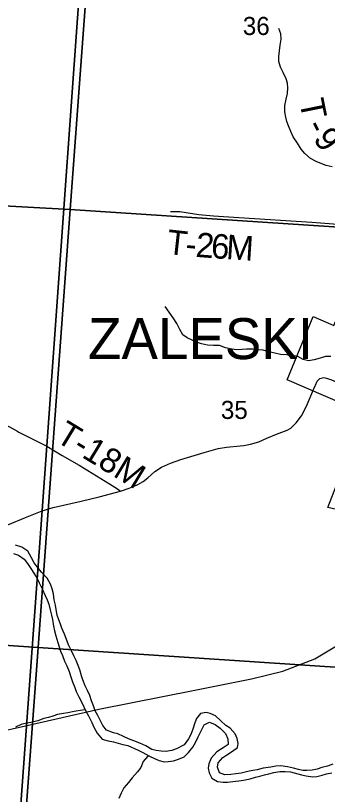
# Model space of a CAD drawing. Extents: x 0 to 34, y 0 to 22.
# Drawn here: x 5.215 to 5.937, y 16.597 to 18.398 of the extents above; entities that cross this region are included whole.
import ezdxf

# ---------------------------------------------------------------- set-up
doc = ezdxf.new("R2010")
doc.units = 0
for name, color, linetype in [('GM_X_Corporation', 7, 'Continuous'), ('GM_X_Corporation_Text', 7, 'Continuous'), ('GM_X_Major_River', 7, 'Continuous'), ('GM_X_Minor_River', 7, 'Continuous'), ('GM_X_Rail_Line', 7, 'Continuous'), ('GM_X_Section', 7, 'Continuous'), ('GM_X_Section_Text', 7, 'Continuous'), ('GM_X_State_Route', 7, 'Continuous'), ('GM_X_Township_Road', 7, 'Continuous'), ('GM_X_Township_Road_Text', 7, 'Continuous'), ('SC_Scratch1', 7, 'Continuous')]:
    doc.layers.add(name, color=color, linetype=linetype)

msp = doc.modelspace()

# ---------------------------------------------------------------- linework, layer by layer
at = {"layer": 'GM_X_Corporation'}
msp.add_lwpolyline([(6.2264, 17.1339), (6.0126, 17.2209), (6.0141, 17.2532), (5.9678, 17.2531), (5.9382, 17.2604), (6.023, 17.4781), (5.8434, 17.5552), (5.9039, 17.7022), (5.952, 17.6811), (6.1661, 18.1773), (6.6117, 17.9917), (6.5173, 17.6859), (6.5005, 17.6619), (6.4701, 17.6297), (6.4392, 17.6123), (6.4283, 17.605)], close=True, dxfattribs=at)
at = {"layer": 'GM_X_Major_River'}
for points in [[(5.7642, 16.6523), (5.7525, 16.6498), (5.7369, 16.6461), (5.7251, 16.6443), (5.713, 16.6428), (5.6997, 16.6422), (5.6872, 16.6464), (5.6827, 16.6598), (5.6843, 16.6696), (5.6946, 16.6821), (5.7042, 16.6884), (5.7171, 16.6967), (5.7285, 16.705), (5.7305, 16.7148), (5.7283, 16.7258), (5.7231, 16.7365), (5.7121, 16.7498), (5.702, 16.7564), (5.6903, 16.7671), (5.6774, 16.7782), (5.6657, 16.784), (5.6562, 16.7859), (5.643, 16.7837), (5.6334, 16.7724), (5.6299, 16.7626), (5.6253, 16.7478), (5.621, 16.735), (5.6149, 16.7251), (5.6049, 16.7116), (5.5878, 16.7018), (5.5764, 16.6981), (5.5627, 16.6959), (5.5521, 16.6964), (5.5407, 16.6984), (5.5305, 16.7003), (5.5162, 16.7088), (5.5025, 16.715), (5.4885, 16.7204), (5.4761, 16.7254), (5.4651, 16.7308), (5.4515, 16.7366), (5.4413, 16.7393), (5.4257, 16.7455), (5.4167, 16.7558), (5.4115, 16.7669), (5.4051, 16.779), (5.3991, 16.7897), (5.3954, 16.8015), (5.3905, 16.8129), (5.3868, 16.8255), (5.3816, 16.8369), (5.3756, 16.8476), (5.3707, 16.8613), (5.3678, 16.8708), (5.3637, 16.8845), (5.36, 16.8951), (5.3551, 16.9061), (5.3495, 16.9168), (5.3446, 16.9286), (5.3375, 16.9427), (5.3323, 16.9575), (5.3282, 16.9674), (5.3222, 16.9811), (5.3185, 16.9907), (5.3148, 17.0005), (5.3114, 17.0112), (5.3085, 17.0245), (5.307, 17.0344), (5.3045, 17.0469), (5.3023, 17.0602), (5.2997, 17.0724), (5.2956, 17.083), (5.2877, 17.0967), (5.2749, 17.1109), (5.2648, 17.1231), (5.258, 17.1326), (5.2509, 17.1456), (5.243, 17.1593), (5.229, 17.1681), (5.2146, 17.1732)], [(5.2103, 17.1538), (5.2217, 17.1503), (5.2349, 17.1404), (5.2428, 17.1305), (5.2503, 17.119), (5.2574, 17.108), (5.265, 17.0958), (5.2694, 17.0862), (5.2766, 17.0722), (5.2837, 17.0569), (5.2881, 17.0466), (5.2915, 17.0364), (5.2952, 17.0238), (5.2981, 17.0109), (5.3004, 17.001), (5.3029, 16.9855), (5.3051, 16.9748), (5.3081, 16.9634), (5.3125, 16.9478), (5.3155, 16.9379), (5.3192, 16.9277), (5.3237, 16.9181), (5.3282, 16.9052), (5.3334, 16.8942), (5.339, 16.8812), (5.3424, 16.8706), (5.3468, 16.8573), (5.3517, 16.8443), (5.355, 16.8344), (5.3614, 16.8222), (5.3666, 16.812), (5.3726, 16.7994), (5.3779, 16.7895), (5.3839, 16.7781), (5.3913, 16.7628), (5.3962, 16.7522), (5.4037, 16.7385), (5.4157, 16.7247), (5.4294, 16.7208), (5.4415, 16.7181), (5.4525, 16.7153), (5.4631, 16.7122), (5.4744, 16.7095), (5.499, 16.6994), (5.5092, 16.694), (5.5251, 16.6852), (5.5364, 16.6794), (5.547, 16.6748), (5.5588, 16.6724), (5.5683, 16.6727), (5.5804, 16.6742), (5.5918, 16.6779), (5.6051, 16.6839), (5.6151, 16.6933), (5.6254, 16.7057), (5.6311, 16.7171), (5.6373, 16.7295), (5.6515, 16.7575), (5.6637, 16.7639), (5.6769, 16.7581), (5.6883, 16.7496), (5.7011, 16.7378), (5.7063, 16.7252), (5.707, 16.7123), (5.6959, 16.7041), (5.6807, 16.6951), (5.6681, 16.6807), (5.6623, 16.6671), (5.6607, 16.6573), (5.6629, 16.6466), (5.6693, 16.6341), (5.6825, 16.6268), (5.6958, 16.6248), (5.7056, 16.6251)], [(5.9494, 16.6669), (5.9369, 16.6624), (5.9243, 16.6587), (5.9129, 16.6554), (5.9019, 16.6528), (5.8894, 16.6518), (5.8799, 16.6522), (5.8701, 16.6542), (5.8583, 16.6573), (5.8447, 16.6608), (5.8292, 16.6629), (5.8174, 16.6622), (5.8056, 16.66), (5.7878, 16.6571), (5.7745, 16.6538), (5.7642, 16.6523)], [(5.7056, 16.6251), (5.7178, 16.6265), (5.7315, 16.6283), (5.7428, 16.6297), (5.758, 16.633), (5.7702, 16.6363), (5.7801, 16.6389), (5.7911, 16.6419), (5.8013, 16.6441), (5.8131, 16.647), (5.8268, 16.65), (5.8389, 16.6499), (5.8511, 16.6487), (5.8768, 16.642), (5.8874, 16.6397), (5.9026, 16.6376), (5.9121, 16.6383), (5.925, 16.6409), (5.9345, 16.6439), (5.947, 16.6464)]]:
    msp.add_lwpolyline(points, dxfattribs=at)
at = {"layer": 'GM_X_Minor_River'}
for points in [[(5.9479, 18.0479), (5.9343, 18.0509), (5.9241, 18.055), (5.9112, 18.0603), (5.8979, 18.0674), (5.8846, 18.0788), (5.8763, 18.089), (5.8675, 18.1026), (5.8576, 18.1178), (5.8519, 18.1299), (5.8466, 18.1432), (5.8431, 18.153), (5.8408, 18.1629), (5.8385, 18.1754), (5.8381, 18.1902), (5.8414, 18.2049), (5.8444, 18.2175), (5.8455, 18.2311), (5.8443, 18.2417), (5.8417, 18.2516), (5.8344, 18.266), (5.828, 18.2785), (5.8245, 18.2914), (5.8241, 18.3035), (5.8256, 18.3164), (5.8278, 18.3293), (5.83, 18.3433), (5.8288, 18.3558), (5.8243, 18.368)], [(5.9452, 17.6095), (5.9327, 17.6091), (5.9199, 17.6053), (5.9059, 17.6014), (5.893, 17.5991), (5.8809, 17.6025), (5.8684, 17.6093), (5.8551, 17.6119), (5.8418, 17.613), (5.8286, 17.6138), (5.815, 17.6168), (5.8013, 17.6201), (5.7881, 17.6239), (5.7763, 17.625), (5.7642, 17.6261), (5.7494, 17.6265), (5.7396, 17.6257), (5.7264, 17.6249), (5.712, 17.6271), (5.7006, 17.6294), (5.6873, 17.635), (5.6729, 17.635), (5.6589, 17.6357), (5.6457, 17.6387), (5.6362, 17.6421), (5.6241, 17.647), (5.6119, 17.6527), (5.6021, 17.6595), (5.5948, 17.672), (5.588, 17.686), (5.5796, 17.6992), (5.5701, 17.7121), (5.561, 17.725)], [(5.3763, 16.7925), (5.3695, 16.7917), (5.3505, 16.7886), (5.3358, 16.7855), (5.3259, 16.784), (5.3119, 16.7813), (5.301, 16.7778), (5.2908, 16.7744), (5.2802, 16.7721), (5.2662, 16.7671), (5.2503, 16.7629), (5.2401, 16.7614), (5.2276, 16.7583), (5.2144, 16.7519)], [(5.5255, 16.685), (5.5205, 16.684), (5.5099, 16.6726), (5.5046, 16.6589), (5.4975, 16.649), (5.485, 16.635), (5.4764, 16.6239), (5.4658, 16.6118), (5.4594, 16.5993), (5.4538, 16.5871)]]:
    msp.add_lwpolyline(points, dxfattribs=at)
at = {"layer": 'GM_X_Rail_Line'}
msp.add_lwpolyline([(5.1686, 16.7396), (5.2381, 16.7552), (5.4076, 16.7935), (5.6302, 16.838), (5.761, 16.8642), (5.834, 16.8816), (5.9075, 16.9106), (5.9775, 16.9517), (6.0279, 16.9921), (6.0831, 17.0404), (6.1385, 17.1164), (6.1838, 17.204), (6.3397, 17.5908), (6.4017, 17.7369), (6.4258, 17.8052), (6.4372, 17.8653), (6.4459, 17.9321), (6.4566, 18.0231), (6.4686, 18.0692), (6.4811, 18.1076), (6.5022, 18.1582), (6.5679, 18.2873), (6.8025, 18.728)], dxfattribs=at)
at = {"layer": 'GM_X_Section'}
for points in [[(4.3808, 19.0475), (4.4009, 19.0464), (5.4174, 18.9797), (5.3412, 17.9492), (4.3187, 18.0057)], [(5.4174, 18.9797), (6.4104, 18.9115), (6.3391, 17.8836), (5.3412, 17.9492)], [(4.3187, 18.0057), (5.3412, 17.9492), (5.2673, 16.9365), (4.2561, 17.0047)], [(5.3412, 17.9492), (6.3391, 17.8836), (6.2455, 16.872), (5.2673, 16.9365)], [(4.2561, 17.0047), (5.2673, 16.9365), (5.1915, 15.9177), (4.189, 15.9719)], [(6.2455, 16.872), (6.2183, 16.4683), (6.1917, 16.0616), (6.1792, 15.8658), (5.1915, 15.9177), (5.2673, 16.9365)]]:
    msp.add_lwpolyline(points, close=True, dxfattribs=at)
at = {"layer": 'GM_X_State_Route'}
for points in [[(5.9096, 17.5435), (5.9129, 17.5523), (5.9196, 17.5583), (5.9283, 17.5605), (5.9347, 17.5595), (5.9466, 17.5555), (6.0284, 17.5194), (6.0451, 17.5141), (6.0517, 17.5157), (6.0577, 17.5236), (6.081, 17.5786), (6.1142, 17.6594), (6.1263, 17.6832), (6.139, 17.68), (6.1519, 17.6753), (6.1568, 17.6748), (6.163, 17.6763), (6.1677, 17.679), (6.1717, 17.6877), (6.1791, 17.707), (6.2101, 17.6944)], [(5.458, 17.2982), (5.4776, 17.3052), (5.4893, 17.3099), (5.4982, 17.3134), (5.5103, 17.3205), (5.5207, 17.3285), (5.5371, 17.3431), (5.553, 17.3535), (5.5733, 17.3627), (5.5978, 17.3709), (5.6516, 17.3872), (5.6838, 17.3966), (5.7029, 17.3994), (5.7349, 17.4028), (5.7431, 17.4038), (5.751, 17.4053), (5.759, 17.4068), (5.7778, 17.4123), (5.7969, 17.4209), (5.8187, 17.4301), (5.8435, 17.439), (5.8524, 17.444), (5.8646, 17.4559), (5.8767, 17.472), (5.8886, 17.4948), (5.9048, 17.533), (5.9089, 17.5417), (5.9096, 17.5435)], [(5.1972, 17.2203), (5.2376, 17.2374), (5.2763, 17.2528), (5.3017, 17.26), (5.3667, 17.2752), (5.4084, 17.2849), (5.458, 17.2982)]]:
    msp.add_lwpolyline(points, dxfattribs=at)
at = {"layer": 'GM_X_Township_Road'}
for points in [[(5.5736, 17.945), (5.5951, 17.945), (5.6391, 17.9378), (5.6729, 17.9349), (5.7319, 17.931)], [(5.7319, 17.931), (5.9011, 17.92), (5.9906, 17.9133), (6.0155, 17.91), (6.0472, 17.9019), (6.1243, 17.8825)], [(5.163, 17.467), (5.2175, 17.4373)], [(5.2175, 17.4373), (5.2227, 17.4345), (5.2502, 17.4205), (5.2871, 17.402)], [(5.2871, 17.402), (5.323, 17.3808), (5.3619, 17.3578), (5.4223, 17.3208), (5.4382, 17.3111), (5.4506, 17.3034), (5.458, 17.2982)]]:
    msp.add_lwpolyline(points, dxfattribs=at)
at = {"layer": 'SC_Scratch1'}
for points in [[(2.1, 19.1982), (2.1, 14.1), (5.0535, 14.1), (5.0814, 14.5016), (5.1049, 14.8414), (5.1794, 15.9156), (5.2761, 17.2534), (5.2869, 17.4026), (5.3506, 18.2846), (5.3662, 18.4999), (5.4007, 18.9779), (5.182, 18.9932), (4.7997, 19.0196), (4.7394, 19.0241), (4.3628, 19.0495), (3.3448, 19.1146), (2.3572, 19.1804)], [(5.0535, 14.1), (8.9, 14.1), (8.9, 18.7389), (8.2061, 18.7863), (7.2159, 18.8539), (6.8273, 18.8804), (5.9889, 18.9377), (5.4885, 18.9719), (5.4007, 18.9779), (5.3662, 18.4999), (5.3506, 18.2846), (5.2869, 17.4026), (5.2761, 17.2534), (5.1794, 15.9156), (5.1049, 14.8414), (5.0814, 14.5016)]]:
    msp.add_lwpolyline(points, close=True, dxfattribs=at)

# ---------------------------------------------------------------- texts
at = {"layer": 'GM_X_Corporation_Text'}
msp.add_text('ZALESKI', height=0.0947, rotation=0, dxfattribs=at).set_placement((5.3827, 17.6034))
at = {"layer": 'GM_X_Section_Text'}
for s, p in [('36', (5.741, 18.3529)), ('35', (5.6902, 17.465))]:
    msp.add_text(s, height=0.04186, rotation=0, dxfattribs=at).set_placement(p)
at = {"layer": 'GM_X_Township_Road_Text'}
for s, height, rotation, p in [('T', 0.0568, 281.3192, (5.8715, 18.1999)), ('-', 0.0568, 296.9783, (5.8854, 18.1423)), ('9', 0.0568, 307.608, (5.9021, 18.1118)), ('T', 0.0568, 353.6745, (5.5631, 17.847)), ('2', 0.0568, 355.4795, (5.6305, 17.84)), ('6', 0.0568, 356.0682, (5.6661, 17.8372)), ('M', 0.0568, 356.3452, (5.7013, 17.8348)), ('-', 0.0568, 354.7929, (5.6066, 17.8422)), ('T-18M', 0.05682, 328.7331, (5.3047, 17.415))]:
    msp.add_text(s, height=height, rotation=rotation, dxfattribs=at).set_placement(p)

doc.saveas('drawing.dxf')
